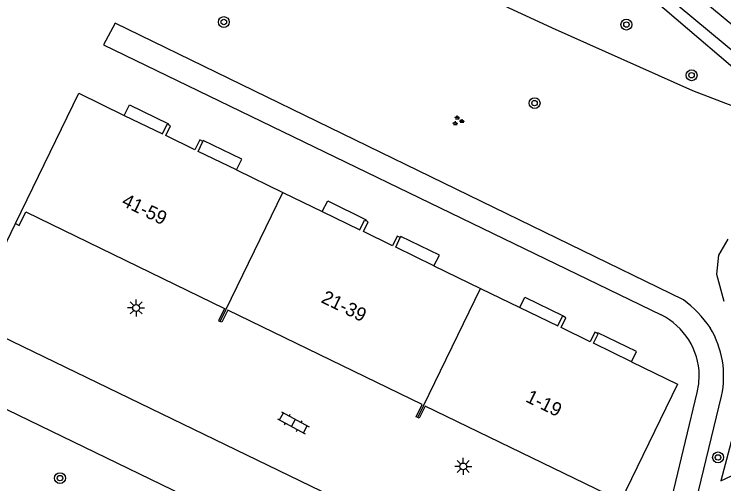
# Model space of a CAD drawing. Extents: x 130998 to 133001, y 398999 to 403002.
# Drawn here: x 131183.7 to 131235.8, y 399051.8 to 399086.3 of the extents above; entities that cross this region are included whole.
import ezdxf

# ---------------------------------------------------------------- set-up
doc = ezdxf.new("R2010")
doc.units = 0
for name, color, linetype in [('gg-anno-huisnummerreeks BGT', 7, 'Continuous'), ('gg-bbg-hoofdgebouw', 7, 'Continuous'), ('gg-bbg-onder overbouw', 7, 'Continuous'), ('gg-bbg-pand overbouw', 7, 'Continuous'), ('gg-bbg-tussenscheiding', 7, 'Continuous'), ('gg-knt-verharding', 7, 'Continuous'), ('gg-knt-verharding nz', 7, 'Continuous'), ('gt-grn-groengrens', 7, 'Continuous'), ('gt-symb-boom', 7, 'Continuous'), ('gt-symb-groenvak', 7, 'Continuous'), ('gt-symb-klinker verharding', 7, 'Continuous'), ('gt-symb-lichtmast', 7, 'Continuous')]:
    doc.layers.add(name, color=color, linetype=linetype)

# ---------------------------------------------------------------- blocks, each defined once
blk = doc.blocks.new('gt0-KL1')
at = {"layer": 'gt-symb-klinker verharding'}
for p, q in [((-1.15, 0.3), (1.15, 0.3)), ((-1, -0.3), (-1, 0.3)), ((-0.5, 0.3), (-0.5, 0.45)), ((0, -0.3), (0, 0.3)), ((0.5, 0.3), (0.5, 0.45)), ((1, -0.3), (1, 0.3)), ((-1.15, -0.3), (1.15, -0.3)), ((-0.5, -0.45), (-0.5, -0.3)), ((0.5, -0.45), (0.5, -0.3))]:
    blk.add_line(p, q, dxfattribs=at)
blk = doc.blocks.new('gt0-BOOM')
at = {"layer": 'gt-symb-boom'}
for radius in [0.4, 0.2]:
    blk.add_circle((0, 0), radius, dxfattribs=at)
blk = doc.blocks.new('gt0-LMAST')
at = {"layer": 'gt-symb-lichtmast'}
for p, q in [((-0.005, 0.246), (-0.005, 0.621)), ((-0.182, 0.173), (-0.447, 0.438)), ((0.172, 0.173), (0.437, 0.438)), ((-0.255, -0.004), (-0.63, -0.004)), ((-0.182, -0.181), (-0.447, -0.446)), ((-0.005, -0.254), (-0.005, -0.629)), ((0.437, -0.446), (0.172, -0.181)), ((0.245, -0.004), (0.62, -0.004))]:
    blk.add_line(p, q, dxfattribs=at)
blk.add_circle((-0.005, -0.004), 0.25, dxfattribs=at)
blk = doc.blocks.new('gt0-GRVAK')
at = {"layer": 'gt-symb-groenvak'}
for p, q in [((-0.11, 0.189), (-0.228, 0.24)), ((-0.182, 0.153), (0.088, 0.153)), ((-0.091, 0.211), (-0.156, 0.322)), ((-0.047, 0.214), (-0.047, 0.393)), ((-0.004, 0.211), (0.061, 0.322)), ((0.015, 0.189), (0.133, 0.24)), ((0.262, -0.052), (0.197, 0.059)), ((0.305, -0.049), (0.305, 0.13)), ((0.349, -0.052), (0.414, 0.059)), ((-0.245, -0.228), (-0.363, -0.177)), ((-0.318, -0.264), (-0.047, -0.264)), ((-0.226, -0.206), (-0.291, -0.095)), ((-0.183, -0.203), (-0.183, -0.024)), ((-0.139, -0.206), (-0.074, -0.095)), ((-0.12, -0.228), (-0.002, -0.177)), ((0.243, -0.074), (0.125, -0.023)), ((0.17, -0.11), (0.441, -0.11)), ((0.368, -0.074), (0.486, -0.023))]:
    blk.add_line(p, q, dxfattribs=at)

msp = doc.modelspace()

# ---------------------------------------------------------------- linework, layer by layer
at = {"layer": 'gg-bbg-hoofdgebouw'}
for p, q in [((131200.008, 399074.853), (131203.412, 399073.198)), ((131203.412, 399073.198), (131206.284, 399071.803)), ((131214.477, 399067.822), (131217.902, 399066.157)), ((131217.902, 399066.157), (131220.784, 399064.756))]:
    msp.add_line(p, q, dxfattribs=at)
for points in [[(131183.791, 399070.91), (131188.431, 399080.48), (131191.778, 399078.853)], [(131197.529, 399076.933), (131197.306, 399077.05), (131196.959, 399076.335), (131194.812, 399077.379), (131195.155, 399078.084), (131194.982, 399078.174)], [(131183.791, 399070.91), (131184.061, 399070.78), (131184.541, 399071.77), (131199.13, 399064.682), (131198.693, 399063.783), (131198.81, 399063.726)], [(131212.016, 399069.89), (131211.788, 399069.997), (131211.447, 399069.294), (131209.314, 399070.331), (131209.661, 399071.043), (131209.479, 399071.131)], [(131213.301, 399056.686), (131213.184, 399056.743), (131213.621, 399057.642), (131199.364, 399064.568), (131198.927, 399063.669), (131198.81, 399063.726)], [(131226.492, 399062.843), (131226.293, 399062.942), (131225.954, 399062.244), (131223.821, 399063.28), (131224.174, 399064.006), (131223.96, 399064.11)], [(131228.993, 399060.767), (131232.361, 399059.13), (131227.721, 399049.57)], [(131227.721, 399049.57), (131227.451, 399049.7), (131227.931, 399050.69), (131213.855, 399057.529), (131213.418, 399056.629), (131213.301, 399056.686)]]:
    msp.add_lwpolyline(points, dxfattribs=at)
at = {"layer": 'gg-bbg-onder overbouw'}
for points in [[(131191.778, 399078.853), (131194.57, 399077.496), (131194.916, 399078.208), (131194.982, 399078.174)], [(131200.008, 399074.853), (131197.205, 399076.216), (131197.529, 399076.933)], [(131206.284, 399071.803), (131209.062, 399070.453), (131209.408, 399071.166), (131209.479, 399071.131)], [(131214.477, 399067.822), (131211.695, 399069.174), (131212.016, 399069.89)], [(131220.784, 399064.756), (131223.57, 399063.403), (131223.922, 399064.128), (131223.96, 399064.11)], [(131228.993, 399060.767), (131226.191, 399062.129), (131226.529, 399062.824), (131226.492, 399062.843)]]:
    msp.add_lwpolyline(points, dxfattribs=at)
at = {"layer": 'gg-bbg-pand overbouw'}
for points in [[(131191.778, 399078.853), (131192.146, 399079.618), (131195.014, 399078.236), (131194.982, 399078.174)], [(131200.008, 399074.853), (131200.41, 399075.642), (131197.566, 399077.004), (131197.529, 399076.933)], [(131206.284, 399071.803), (131206.696, 399072.576), (131209.51, 399071.195), (131209.479, 399071.131)], [(131214.477, 399067.822), (131214.892, 399068.6), (131212.058, 399069.977), (131212.016, 399069.89)], [(131220.784, 399064.756), (131221.166, 399065.52), (131223.982, 399064.154), (131223.96, 399064.11)], [(131228.993, 399060.767), (131229.36, 399061.533), (131226.522, 399062.903), (131226.492, 399062.843)]]:
    msp.add_lwpolyline(points, dxfattribs=at)
at = {"layer": 'gg-bbg-tussenscheiding'}
for p, q in [((131198.81, 399063.726), (131203.412, 399073.198)), ((131213.301, 399056.686), (131217.902, 399066.157))]:
    msp.add_line(p, q, dxfattribs=at)
at = {"layer": 'gg-knt-verharding'}
msp.add_line((131182.868, 399068.985), (131183.791, 399070.91), dxfattribs=at)
for points in [[(131255.362, 399067.596), (131251.229, 399071.758), (131240.424, 399082.126), (131228.135, 399092.341), (131218.707, 399100.677), (131210.18, 399106.575), (131202.439, 399110.959), (131201.967, 399111.25)], [(131206.384, 399107.045), (131209.845, 399105.079), (131217.246, 399099.996), (131227.807, 399090.752), (131239.314, 399081.197), (131251.981, 399068.787)], [(131204.162, 399047.064), (131178.356, 399059.572), (131180.381, 399063.797)]]:
    msp.add_lwpolyline(points, dxfattribs=at)
at = {"layer": 'gg-knt-verharding nz'}
msp.add_lwpolyline([(131180.381, 399063.797), (131211.691, 399048.645), (131211.575, 399048.448)], dxfattribs=at)
at = {"layer": 'gt-grn-groengrens'}
for p, q in [((131234.753, 399063.282), (131234.762, 399063.268)), ((131233.261, 399048.684), (131235.593, 399058.263))]:
    msp.add_line(p, q, dxfattribs=at)
for points in [[(131237.916, 399081.089), (131218.461, 399097.696)], [(131216.396, 399088.436), (131223.17, 399085.267), (131233.47, 399080.672), (131236.718, 399079.444)], [(131232.79, 399065.331), (131191.112, 399085.631), (131190.257, 399084.038), (131231.17, 399064.208)], [(131236.045, 399069.778), (131235.371, 399068.589), (131235.213, 399067.203), (131235.767, 399065.222)], [(131231.234, 399047.807), (131233.808, 399058.532), (131233.918, 399059.149), (131233.958, 399059.777)], [(131236.718, 399056.467), (131235.53, 399052.03), (131239.135, 399053.734)]]:
    msp.add_lwpolyline(points, dxfattribs=at)
for centre, radius, start, end in [((131227.473, 399058.272), 8.837, 34.5336, 53.0104), ((131228.889, 399059.68), 5.07, 1.095, 63.2614), ((131228.787, 399059.704), 6.957, 348.0423, 30.8118)]:
    msp.add_arc(centre, radius, start, end, dxfattribs=at)

# ---------------------------------------------------------------- block references
at = {"layer": 'gt-symb-boom'}
for p in [(131199.077, 399085.703), (131228.612, 399085.516), (131233.391, 399081.801), (131221.873, 399079.752), (131235.331, 399053.756), (131187.059, 399052.237)]:
    msp.add_blockref('gt0-BOOM', p, dxfattribs=at)
at = {"layer": 'gt-symb-groenvak'}
msp.add_blockref('gt0-GRVAK', (131216.251, 399078.458), dxfattribs=at)
at = {"layer": 'gt-symb-klinker verharding', "rotation": -28.537337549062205}
msp.add_blockref('gt0-KL1', (131204.18, 399056.297), dxfattribs=at)
at = {"layer": 'gt-symb-lichtmast'}
for p in [(131192.647, 399064.728), (131216.646, 399053.101)]:
    msp.add_blockref('gt0-LMAST', p, dxfattribs=at)

# ---------------------------------------------------------------- texts
at = {"layer": 'gg-anno-huisnummerreeks BGT'}
for s, p in [('41-59', (131191.514, 399072.272)), ('21-39', (131206.148, 399065.162)), ('1-19', (131221.149, 399057.876))]:
    msp.add_text(s, height=1, rotation=334.1, dxfattribs=at).set_placement(p)

doc.saveas('drawing.dxf')
